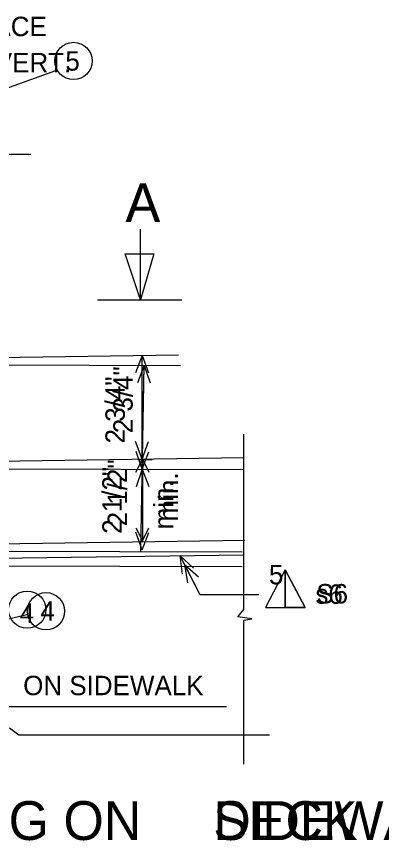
# Model space of a CAD drawing. Extents: x 1509.2 to 1521.3, y 1506 to 1514.6.
# Drawn here: x 1511.957 to 1512.741, y 1509.298 to 1511.067 of the extents above; entities that cross this region are included whole.
import ezdxf

# ---------------------------------------------------------------- set-up
doc = ezdxf.new("R2010")
doc.units = 0
for name, color, linetype in [('Level 2', 7, 'Continuous'), ('Level 3', 7, 'Continuous'), ('Level 4', 7, 'Continuous'), ('Level 6', 7, 'Continuous'), ('Level 60', 7, 'Continuous')]:
    doc.layers.add(name, color=color, linetype=linetype)

msp = doc.modelspace()

# ---------------------------------------------------------------- linework, layer by layer
at = {"layer": 'Level 2'}
msp.add_line((1512.5343, 1509.8786), (1512.5343, 1509.7983), dxfattribs=at)
for points in [[(1512.4919, 1509.7983), (1512.5767, 1509.7983), (1512.5343, 1509.8786)], [(1512.5343, 1509.8786), (1512.5767, 1509.7983), (1512.5343, 1509.7983)]]:
    msp.add_lwpolyline(points, close=True, dxfattribs=at)
at = {"layer": 'Level 3'}
for p, q in [((1512.2236, 1510.4586), (1512.2236, 1510.6102)), ((1512.2236, 1510.4586), (1512.1906, 1510.5574)), ((1512.1906, 1510.5574), (1512.2523, 1510.5574)), ((1512.2523, 1510.5574), (1512.2236, 1510.4586)), ((1512.1313, 1510.4586), (1512.3125, 1510.4586)), ((1511.7425, 1510.3321), (1512.3049, 1510.3405)), ((1512.2268, 1510.3393), (1512.2131, 1510.3018)), ((1512.2268, 1510.3393), (1512.2131, 1510.3018)), ((1512.2268, 1510.1165), (1512.2268, 1510.3393)), ((1512.2268, 1510.3393), (1512.2404, 1510.3018)), ((1512.2268, 1510.3393), (1512.2404, 1510.3018)), ((1512.4451, 1509.7934), (1512.4451, 1510.1704)), ((1512.2268, 1510.1165), (1512.2131, 1510.1541)), ((1512.2268, 1510.1165), (1512.2404, 1510.1541)), ((1510.9693, 1510.0976), (1512.445, 1510.1198)), ((1512.2186, 1510.1157), (1512.2486, 1510.1157)), ((1511.0337, 1509.9216), (1512.4477, 1509.9428)), ((1511.0322, 1509.8914), (1512.445, 1509.9114)), ((1512.308, 1509.9093), (1512.3512, 1509.826)), ((1512.308, 1509.9093), (1512.3132, 1509.8697)), ((1512.308, 1509.9093), (1512.3374, 1509.8823)), ((1512.3512, 1509.826), (1512.4771, 1509.826)), ((1511.7863, 1509.7384), (1511.98, 1509.7828)), ((1512.4325, 1509.7783), (1512.4451, 1509.7934)), ((1512.4627, 1509.7733), (1512.4325, 1509.7783)), ((1512.4451, 1509.7708), (1512.4627, 1509.7733)), ((1512.4451, 1509.4616), (1512.4451, 1509.7708)), ((1511.9423, 1509.5395), (1511.9623, 1509.5244)), ((1511.9623, 1509.5244), (1512.5003, 1509.5244))]:
    msp.add_line(p, q, dxfattribs=at)
msp.add_circle((1512.0208, 1509.79), 0.04, dxfattribs=at)
at = {"layer": 'Level 4'}
for p, q in [((1511.8799, 1510.8929), (1512.042, 1510.9512)), ((1511.3357, 1510.7714), (1511.9883, 1510.7714)), ((1512.2236, 1510.4586), (1512.2236, 1510.6102)), ((1512.2236, 1510.4586), (1512.1906, 1510.5574)), ((1512.1906, 1510.5574), (1512.2523, 1510.5574)), ((1512.2523, 1510.5574), (1512.2236, 1510.4586)), ((1512.1313, 1510.4586), (1512.3125, 1510.4586)), ((1511.7468, 1510.3191), (1512.3093, 1510.3178)), ((1512.2312, 1510.3179), (1512.2168, 1510.2805)), ((1512.2312, 1510.3179), (1512.2168, 1510.2805)), ((1512.2242, 1509.9182), (1512.2312, 1510.3179)), ((1512.2273, 1510.0951), (1512.2312, 1510.3179)), ((1512.2312, 1510.3179), (1512.2442, 1510.2801)), ((1512.2312, 1510.3179), (1512.2442, 1510.2801)), ((1512.4451, 1509.7934), (1512.4451, 1510.1704)), ((1512.2273, 1510.0951), (1512.2143, 1510.1329)), ((1512.2273, 1510.0951), (1512.2143, 1510.1329)), ((1512.2273, 1510.0951), (1512.2416, 1510.1325)), ((1512.2273, 1510.0951), (1512.2416, 1510.1325)), ((1510.9697, 1510.0983), (1512.4456, 1510.0946)), ((1512.2273, 1510.095), (1512.2141, 1510.0573)), ((1512.2273, 1510.095), (1512.2414, 1510.0577)), ((1512.2268, 1509.9219), (1512.2138, 1509.9598)), ((1512.2268, 1509.9219), (1512.2411, 1509.9593)), ((1511.0634, 1509.9207), (1512.4419, 1509.9173)), ((1511.0614, 1509.8897), (1512.4419, 1509.8863)), ((1512.3182, 1509.8903), (1512.3241, 1509.8508)), ((1512.3182, 1509.8903), (1512.348, 1509.8638)), ((1512.3196, 1509.8869), (1512.3512, 1509.826)), ((1512.3512, 1509.826), (1512.4778, 1509.826)), ((1512.4325, 1509.7783), (1512.4451, 1509.7934)), ((1512.4627, 1509.7733), (1512.4325, 1509.7783)), ((1512.4451, 1509.7708), (1512.4627, 1509.7733)), ((1512.4451, 1509.4616), (1512.4451, 1509.7708)), ((1512.4083, 1509.585), (1511.9123, 1509.585)), ((1511.9623, 1509.5244), (1512.5003, 1509.5244))]:
    msp.add_line(p, q, dxfattribs=at)
for centre in [(1512.0798, 1510.9716), (1511.9805, 1509.7934)]:
    msp.add_circle(centre, 0.04, dxfattribs=at)
at = {"layer": 'Level 6'}
msp.add_line((1512.2278, 1510.1165), (1512.2278, 1509.9395), dxfattribs=at)
for points in [[(1512.2138, 1510.0887), (1512.2278, 1510.1164), (1512.2417, 1510.0887)], [(1512.2138, 1509.9688), (1512.2278, 1509.941), (1512.2417, 1509.9688)]]:
    msp.add_lwpolyline(points, dxfattribs=at)

# ---------------------------------------------------------------- texts
at = {"layer": 'Level 2'}
msp.add_text('SECTION THRU RAILING ON', height=0.083334, rotation=0, dxfattribs=at).set_placement((1510.7146, 1509.2988))
at = {"layer": 'Level 3'}
for s, height, rotation, p in [('THIS FACE', 0.04167, 0, (1511.7316, 1511.0248)), ('TO BE VERT.', 0.041667, 0, (1511.7283, 1510.9471)), ('A', 0.0833, 0, (1512.1911, 1510.6255)), ('2 3/4"', 0.04167, 90, (1512.2068, 1510.1722)), ('4', 0.0417, 0, (1512.0089, 1509.7696))]:
    msp.add_text(s, height=height, rotation=rotation, dxfattribs=at).set_placement(p)
for s, height, p in [('S6  ', 0.04167, (1512.6008, 1509.8067)), (' DECK', 0.08333, (1512.3488, 1509.2988))]:
    msp.add_text(s, height=height, dxfattribs=at).set_placement(p)
at = {"layer": 'Level 4'}
for s, height, rotation, p in [('5', 0.0417, 0, (1512.0623, 1510.9508)), ('A', 0.0833, 0, (1512.1918, 1510.6255)), ('2 3/4"', 0.04167, 90, (1512.1899, 1510.1503)), ('2 1/2"', 0.04167, 90, (1512.1832, 1509.9562)), ('min.', 0.04167, 90, (1512.294, 1509.9659)), ('4', 0.0417, 0, (1511.9645, 1509.765))]:
    msp.add_text(s, height=height, rotation=rotation, dxfattribs=at).set_placement(p)
for s, height, p in [('s6  ', 0.04167, (1512.5989, 1509.8059)), ('ON SIDEWALK', 0.041667, (1511.9718, 1509.6097)), (' SIDEWALK', 0.08333, (1512.3488, 1509.2988))]:
    msp.add_text(s, height=height, dxfattribs=at).set_placement(p)
at = {"layer": 'Level 6'}
for s, p in [('2 1/2"', (1512.1947, 1509.9723)), ('min.', (1512.3043, 1509.9828))]:
    msp.add_text(s, height=0.04167, rotation=90, dxfattribs=at).set_placement(p)
at = {"layer": 'Level 60'}
msp.add_text('5', height=0.0417, dxfattribs=at).set_placement((1512.4991, 1509.8478))

doc.saveas('drawing.dxf')
